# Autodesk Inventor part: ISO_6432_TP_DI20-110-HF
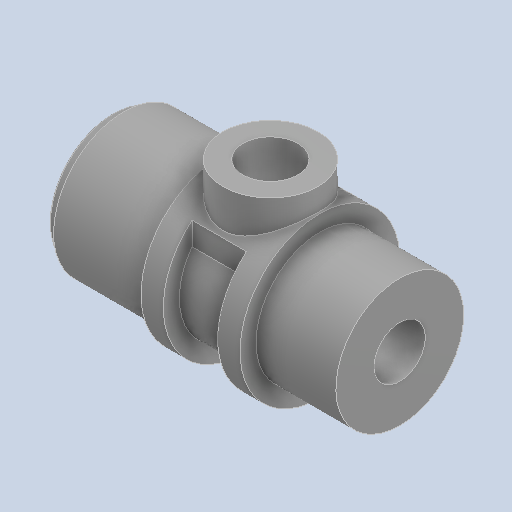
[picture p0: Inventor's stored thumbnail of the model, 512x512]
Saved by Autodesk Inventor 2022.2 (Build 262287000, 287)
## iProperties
Created: 2024-10
Part Number: ISO_6432_TP_DI20-110-HF
Material: Generico
Document SubType Name: Modeling
Designer: 18907419
Density: 1 g/cm^3
Appearance: Default
Author: 18907419
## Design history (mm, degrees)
feature "Solid1"
node "Solido1"
